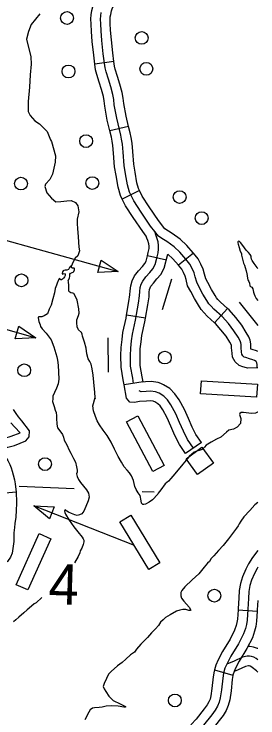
# Model space of a CAD drawing. Extents: x 653372 to 905732, y 627442 to 787275.
# Drawn here: x 726770 to 728673, y 744286 to 749788 of the extents above; entities that cross this region are included whole.
import ezdxf

# ---------------------------------------------------------------- set-up
doc = ezdxf.new("R2010")
doc.units = 0
for name, color, linetype in [('32', 7, 'Continuous'), ('35', 7, 'Continuous'), ('45', 7, 'Continuous'), ('5', 7, 'Continuous'), ('56', 7, 'Continuous'), ('57', 7, 'Continuous'), ('9', 7, 'Continuous')]:
    doc.layers.add(name, color=color, linetype=linetype)

msp = doc.modelspace()

# ---------------------------------------------------------------- linework, layer by layer
at = {"layer": '32'}
for p, q in [((727549, 749417.2), (727400.3, 749397.6)), ((727662.8, 748910.5), (727516.8, 748876.1)), ((727748.1, 748408.3), (727613.4, 748342.4)), ((727958.1, 747865.3), (727811.6, 747897.1)), ((728170.2, 747919.1), (728052.5, 747826.1)), ((727795.8, 747409.9), (727648, 747435.3)), ((728435.5, 747486.9), (728335.1, 747375.5)), ((728672.8, 747022.8), (728590.8, 747020.6)), ((727776.6, 746912), (727628.4, 746889)), ((728517.5, 745130.9), (728667.2, 745121.7)), ((728334.1, 744661), (728478.3, 744619.7))]:
    msp.add_line(p, q, dxfattribs=at)
for points in [[(727400.3, 749397.6), (727391, 749467.9), (727380, 749573.8), (727373.7, 749651.4), (727370.6, 749709.6), (727369.8, 749750), (727370.7, 749781.4), (727376.6, 749815.2), (727386.4, 749854.6), (727399, 749893.2), (727420.4, 749938.1), (727430.9, 749958.4)], [(727549, 749417.2), (727540, 749485.5), (727529.3, 749587.7), (727523.4, 749661.4), (727520.5, 749715.1), (727519.8, 749749.2), (727520.4, 749766.2), (727523.5, 749784.3), (727530.7, 749813.2), (727538.5, 749837.3), (727554.9, 749871.5), (727564.3, 749889.9)], [(727444.8, 749749.6), (727445.5, 749773.8), (727450.1, 749799.7)], [(727702.5, 746900.5), (727696.3, 746940.7), (727679.5, 747034.5), (727678.4, 747119.3), (727680.1, 747176.1), (727687.4, 747234.5), (727692.8, 747286.9), (727717.4, 747396.6), (727740, 747528.1), (727749.2, 747585.9), (727750.2, 747619.4), (727753.9, 747650), (727761.2, 747675.9), (727774.1, 747701.5), (727799.2, 747733.4), (727828.2, 747767), (727853.2, 747796), (727871, 747829.9), (727884.6, 747880.7), (727893.3, 747920.5), (727897.9, 747950.2), (727897.8, 747978.1), (727894, 748007.1), (727884.8, 748040), (727877, 748061.6), (727867.6, 748088), (727834.4, 748131.3), (727762.3, 748240.5), (727704.4, 748327), (727670.2, 748397), (727654.2, 748452.4), (727640.3, 748539), (727629.2, 748604.5), (727621.2, 748708.1), (727615.6, 748770.6), (727609.3, 748809.9), (727601.9, 748841.8), (727570.5, 748975), (727551.3, 749079.2), (727547, 749120.4), (727540.7, 749159.7), (727523.9, 749219.8), (727506.1, 749279), (727487.3, 749336.3), (727479.9, 749367.3), (727465.5, 749476.7), (727454.6, 749580.8), (727448.5, 749656.4), (727445.6, 749712.3), (727444.8, 749749.6)], [(727662.8, 748910.5), (727643.9, 748990.4), (727625.6, 749090), (727621.3, 749130.2), (727614.1, 749175.7), (727595.9, 749240.6), (727577.7, 749301.4), (727559.6, 749356.8), (727553.7, 749381), (727549, 749417.2)], [(727516.8, 748876.1), (727497.1, 748959.6), (727477, 749068.5), (727472.6, 749110.5), (727467.3, 749143.6), (727451.8, 749198.9), (727434.5, 749256.5), (727415.1, 749315.9), (727406, 749353.6), (727400.3, 749397.6)], [(727613.4, 748342.4), (727599.9, 748369.9), (727580.8, 748436), (727566.3, 748526.8), (727554.7, 748595.3), (727546.4, 748701.9), (727541.1, 748761.4), (727535.7, 748795.5), (727528.9, 748824.7), (727516.8, 748876.1)], [(727748.1, 748408.3), (727740.4, 748424.1), (727727.5, 748468.8), (727714.3, 748551.1), (727703.7, 748613.6), (727695.9, 748714.3), (727690.1, 748779.9), (727683, 748824.4), (727674.9, 748858.9), (727662.8, 748910.5)], [(727946.6, 748108.2), (727895.6, 748174.8), (727824.8, 748282.1), (727769.5, 748364.5), (727748.1, 748408.3)], [(727817.4, 747924.3), (727819.5, 747934.3), (727822.9, 747955.9), (727822.8, 747973.1), (727820.3, 747992), (727813.3, 748017.2), (727806.4, 748036.4), (727800.9, 748051.7), (727773.3, 748087.8), (727699.9, 748199), (727639.2, 748289.5), (727613.4, 748342.4)], [(728170.2, 747919.1), (728168.4, 747921.3), (728118.3, 747978.9), (728066.9, 748027.5), (728004.4, 748073.2), (727946.6, 748108.2)], [(728666.4, 747029), (728667.5, 747048.6), (728664.5, 747061), (728658.7, 747071.3), (728646.6, 747079.5), (728633.9, 747086.1), (728606.1, 747094.2), (728579.4, 747102.3), (728565, 747107.2), (728554.1, 747116.5), (728547.7, 747128.5), (728545.4, 747145.4), (728541.5, 747182.5), (728542.1, 747205.3), (728540.3, 747217.2), (728533.4, 747233.1), (728517.5, 747261.6), (728485.9, 747313), (728442.2, 747368.2), (728394.5, 747422.9), (728329.2, 747481.8), (728307.4, 747504.3), (728288.9, 747523.4), (728273.4, 747549.7), (728244.2, 747599.8), (728215.6, 747654.5), (728194.8, 747692.1), (728184.3, 747734.5), (728174.2, 747766.6), (728159.5, 747799.5), (728142, 747833.7), (728110.7, 747873.4), (728064.1, 747926.9), (728018.8, 747969.8), (727962.8, 748010.8), (727923.7, 748034.4), (727896.3, 748053.1), (727867.6, 748088)], [(727648, 747435.3), (727666, 747540.4), (727674.3, 747592.9), (727675.3, 747625), (727680.1, 747664.8), (727690.9, 747703.1), (727710.4, 747742), (727741.4, 747781.1), (727771.4, 747816), (727790.8, 747838.5), (727800.7, 747857.4), (727811.7, 747898.4), (727817.4, 747924.4)], [(727795.8, 747409.9), (727814, 747515.9), (727824, 747578.8), (727825, 747613.7), (727827.6, 747635.2), (727831.4, 747648.6), (727837.7, 747661.1), (727857.1, 747685.6), (727884.9, 747718), (727915.6, 747753.5), (727941.3, 747802.5), (727970.7, 747912.1)], [(728052.9, 747825.5), (728009.9, 747875), (727970.7, 747912.1)], [(728435.5, 747486.9), (728381.3, 747535.8), (728361.3, 747556.5), (728349, 747569.2), (728338.2, 747587.6), (728309.9, 747636.1), (728281.7, 747690), (728265.3, 747719.7), (728256.6, 747754.9), (728244.4, 747793.2), (728227.2, 747831.9), (728205.4, 747874.4), (728170.2, 747919.1)], [(728335.1, 747375.5), (728277, 747427.8), (728253.5, 747452.2), (728228.8, 747477.6), (728208.7, 747511.7), (728178.6, 747563.5), (728149.5, 747619), (728124.4, 747664.6), (728112.1, 747714.2), (728104, 747739.9), (728091.8, 747767.2), (728078.6, 747793), (728052.5, 747826.1)], [(727628.4, 746889), (727622.3, 746928.4), (727604.6, 747027.4), (727603.4, 747119.9), (727605.2, 747181.9), (727612.9, 747243), (727618.6, 747299), (727643.8, 747411.1), (727648, 747435.3)], [(728672.8, 747150.4), (728661.9, 747156), (728627.5, 747166.1), (728618.3, 747168.9), (728616.6, 747185.4), (728617.3, 747210.1), (728612.9, 747238.1), (728600.8, 747266.2), (728582.2, 747299.5), (728547.5, 747356.1), (728499.8, 747416.2), (728448, 747475.6), (728435.5, 747486.9)], [(727776.6, 746912), (727770.3, 746953), (727754.5, 747041.7), (727753.4, 747118.7), (727754.9, 747170.2), (727761.9, 747226), (727767, 747274.8), (727791, 747382), (727795.8, 747409.9)], [(728590.8, 747020.6), (728584.7, 747022.3), (728556.4, 747030.9), (728527.3, 747040.8), (728494.6, 747068.7), (728475.2, 747105.1), (728470.9, 747136.4), (728466.3, 747179.7), (728466.9, 747198), (728466.1, 747199.9), (728452.8, 747223.7), (728424.4, 747270), (728384.5, 747320.2), (728340.9, 747370.2), (728335.1, 747375.5)], [(728672.8, 745594.8), (728629.7, 745539.9), (728600.4, 745489.7), (728577.9, 745448), (728551.7, 745389), (728537.3, 745337.8), (728527.1, 745281.9), (728523.8, 745223.1), (728518, 745140.1), (728517.5, 745130.9)], [(728672.8, 745465), (728665.8, 745453), (728645.3, 745414.9), (728622.4, 745363.5), (728610.5, 745320.9), (728601.7, 745273.1), (728598.7, 745218.4), (728592.9, 745135.1), (728587.7, 745050.5), (728583.3, 745015.9), (728574.7, 744985.6), (728560.6, 744942.3), (728520.9, 744865.4), (728462.6, 744767.7), (728429.6, 744706.6), (728415.7, 744673.6), (728404.5, 744634.6), (728398, 744596.7), (728388.7, 744506.7), (728379.4, 744442.8), (728370.4, 744408.4), (728357.5, 744378.7), (728339.1, 744346.6), (728312, 744311.3), (728247.5, 744229.2)], [(728672.8, 745202.8), (728667.7, 745130.2), (728667.2, 745121.7)], [(728517.5, 745130.9), (728512.9, 745057.5), (728509.6, 745031), (728502.9, 745007.5), (728491.1, 744971.3), (728455.3, 744901.8), (728397.3, 744804.7), (728361.8, 744739.1), (728344.8, 744698.5), (728334.1, 744661)], [(728667.2, 745121.7), (728662.4, 745043.5), (728657, 745000.9), (728646.4, 744963.8), (728630, 744913.3), (728586.5, 744828.9), (728527.8, 744730.6), (728497.3, 744674.2), (728486.6, 744648.7), (728478.3, 744619.7)], [(728334.1, 744661), (728331.3, 744651.2), (728323.7, 744606.9), (728314.2, 744515.9), (728305.8, 744457.8), (728299.3, 744433), (728290.3, 744412.4), (728276.5, 744388.2), (728252.8, 744357.4), (728189.8, 744277.1), (728151.6, 744233.6), (728148.1, 744230.5)], [(728478.3, 744619.7), (728477.7, 744617.9), (728472.4, 744586.5), (728463.1, 744497.4), (728453, 744427.9), (728441.4, 744383.8), (728424.6, 744345.1), (728401.7, 744305), (728371.3, 744265.3), (728288.8, 744160.3)]]:
    msp.add_lwpolyline(points, dxfattribs=at)
at = {"layer": '35'}
for points in [[(726969.3, 749788.9), (726903.8, 749707.1), (726880.8, 749652.7), (726867.7, 749592.6), (726899.9, 749453.2), (726903.8, 749396.6), (726895.3, 749313.6), (726889.3, 749217.5), (726880.3, 749104.6), (726878.8, 749027.5)], [(726878.8, 749027.5), (726896.1, 748995.2), (726932.3, 748953), (726967.7, 748929), (727027.8, 748870.3), (727053.7, 748804.1), (727062.4, 748792.8), (727092.2, 748679.5), (727090.2, 748629.6), (727068.7, 748537.8)], [(727068.7, 748537.8), (727049.9, 748495.5), (727013.8, 748459.8), (727009.8, 748439.9), (727025.1, 748390.9), (727062.2, 748348), (727096.5, 748320.3), (727133.3, 748322.2), (727182, 748329.4), (727215.4, 748329.7), (727250.1, 748315.6), (727266, 748288.4), (727274.7, 748243), (727262.9, 748184.9), (727261.8, 748148.1), (727265.8, 748112.9), (727268.8, 748045.9), (727274.7, 747967.2), (727278.9, 747936.9), (727267.6, 747897.2), (727245.4, 747879.4), (727229.5, 747851.5), (727214.5, 747815.8)]]:
    msp.add_lwpolyline(points, dxfattribs=at)
at = {"layer": '45'}
for p, q in [((728232.3, 746438.1), (728108.7, 746353.2)), ((726635.6, 746041.2), (726785.1, 746053.6))]:
    msp.add_line(p, q, dxfattribs=at)
for points in [[(727860.1, 746759.8), (727855.7, 746761.6), (727832.7, 746764.4), (727803.7, 746763.1), (727749.3, 746759.3), (727710.7, 746751.8), (727671.9, 746755), (727646.3, 746786.4), (727628.4, 746889)], [(727916, 746899), (727893.6, 746908), (727838.6, 746914.9), (727795, 746912.8), (727774.7, 746911.4), (727774.7, 746911.4)], [(728232.3, 746438.1), (728188.7, 746501.7), (728159.3, 746558.9), (728129.8, 746625.4), (728099, 746697.2), (728057.5, 746772.8), (728025, 746820.1), (727986.1, 746860.2), (727936.1, 746890.9), (727916, 746899)], [(728170.5, 746395.6), (728124.1, 746463.1), (728091.6, 746526.5), (728061.1, 746595.4), (728031.5, 746664.3), (727993.5, 746733.4), (727966.8, 746772.4), (727938.8, 746801.2), (727902.2, 746823.7), (727874.6, 746834.8), (727835.7, 746839.7), (727799.3, 746838), (727762, 746835.4), (727745.5, 746842.4)], [(728108.7, 746353.2), (728059.6, 746424.6), (728023.9, 746494.2), (727992.3, 746565.4), (727964, 746631.4), (727929.6, 746694), (727908.6, 746724.7), (727891.5, 746742.2), (727868.4, 746756.5), (727860.1, 746759.8)], [(726662.7, 746381.1), (726721.4, 746401.8), (726771.9, 746416.5), (726861.1, 746452.8), (726887.5, 746483), (726888.9, 746529.4), (726829.8, 746608.6), (726803.2, 746640.5), (726785.1, 746664.5), (726766.2, 746697.9), (726766.3, 746697.8)], [(726817.9, 746514.3), (726774.3, 746558), (726744.4, 746593.9)], [(726492.6, 746424.2), (726516.8, 746426.9), (726554.4, 746435.3), (726613.9, 746447.9), (726662.1, 746460.4), (726698.4, 746473.3), (726748, 746487.7), (726817.9, 746514.3)], [(726662.7, 746381.1), (726697.1, 746335.8), (726720.2, 746298.2), (726736.9, 746266.9), (726746.8, 746240.2), (726753.7, 746214.3), (726761.8, 746187.2), (726772.4, 746147.6), (726777.8, 746115.2), (726783.5, 746072.1), (726785.1, 746053.6)], [(726785.1, 746053.6), (726787.1, 746028.6), (726788.2, 745992.4), (726788.9, 745960.9), (726786.8, 745909.5), (726784.1, 745855), (726776.2, 745805.8), (726771.6, 745774.5), (726768, 745731.9), (726766.5, 745664.5), (726761, 745610.1), (726755, 745573.6), (726742.4, 745542.9), (726718.8, 745507.9), (726673.6, 745490.1), (726643, 745492.9), (726617.2, 745498.4), (726584.9, 745515.8), (726574.8, 745526.1)], [(728672.8, 744828.5), (728670.2, 744829.9), (728639.5, 744840.2), (728611.1, 744844.5), (728594.3, 744844)], [(728672.8, 744740.6), (728658.2, 744751.5), (728640.7, 744760.7), (728621.9, 744767), (728606.5, 744769.3), (728588.7, 744768.8), (728551.9, 744760.3), (728487.9, 744730.4), (728429.6, 744706.6)], [(728614.4, 744689.8), (728611.2, 744691.5), (728604.2, 744693.8), (728601.9, 744694.2), (728598.3, 744694.1), (728576.5, 744689), (728517.9, 744661.7), (728486.7, 744648.9)], [(728672.8, 744644.1), (728661.7, 744653.8), (728627.4, 744680.9), (728618.1, 744687.8), (728614.4, 744689.8)]]:
    msp.add_lwpolyline(points, dxfattribs=at)
at = {"layer": '5'}
for points in [[(727239.8, 746076.1), (726808.9, 746094.2)], [(727863.2, 746049.8), (727769.9, 746053.7)]]:
    msp.add_lwpolyline(points, dxfattribs=at)
at = {"layer": '56'}
for p, q in [((727422.1, 747767.2), (727449.5, 747865.4)), ((727449.5, 747865.4), (727583.2, 747775.2)), ((727583.2, 747775.2), (727422.1, 747767.2)), ((726778.2, 747249.5), (726806.3, 747347.5)), ((726806.3, 747347.5), (726939.3, 747256.2)), ((726939.3, 747256.2), (726778.2, 747249.5)), ((727046, 745841.3), (726922.6, 745945.1)), ((726922.6, 745945.1), (727083.6, 745936.1)), ((727083.6, 745936.1), (727046, 745841.3))]:
    msp.add_line(p, q, dxfattribs=at)
for points in [[(726156.2, 748637.7), (726026.1, 748209.4), (727583.2, 747775.2)], [(727999.3, 747716.2), (727926.7, 747477)], [(728526.4, 747536.1), (728672.8, 747352.4)], [(726373.8, 747418.8), (726939.3, 747256.2)], [(727502.6, 747257.9), (727502.7, 746987.9)], [(727708.4, 745633.1), (726922.6, 745945.1)]]:
    msp.add_lwpolyline(points, dxfattribs=at)
for points in [[(728226, 746820), (728231.9, 746919.8), (728668.6, 746894.1), (728662.7, 746794.3)], [(727646.7, 746599.7), (727735, 746646.5), (727939.8, 746259.9), (727851.4, 746213.1)], [(727594.6, 745819.9), (727680, 745872), (727907.7, 745498.4), (727822.3, 745446.4)], [(726964.5, 745726.5), (727055.8, 745685.6), (726877.2, 745286.3), (726785.9, 745327.1)]]:
    msp.add_lwpolyline(points, close=True, dxfattribs=at)
for centre in [(727182.8, 749757.4), (727765.5, 749602), (727194.1, 749339.4), (727801.7, 749360.1), (727331.9, 748795), (726823, 748463), (727380.1, 748467.1), (728061.8, 748357.7), (728234, 748193), (726827.2, 747706.5), (727946.2, 747102.7), (726848.7, 747004), (727010.6, 746270.1), (728333.1, 745241.2), (728024.7, 744422.3)]:
    msp.add_circle(centre, 50, dxfattribs=at)
at = {"layer": '57'}
msp.add_lwpolyline([(728202, 746187.8), (728111.7, 746311.3), (728235.2, 746401.6), (728325.5, 746278.1)], close=True, dxfattribs=at)
at = {"layer": '9'}
for points in [[(728672.8, 747797.6), (728667, 747805.9), (728644.4, 747838.5), (728627.8, 747863.1), (728622.5, 747873.4), (728619.5, 747886.4), (728619.8, 747895.9), (728611.2, 747907.9), (728599.3, 747923.4), (728581.4, 747943.6), (728555.5, 747978.6), (728536.1, 748002.8), (728529, 748010.8), (728520.7, 748012.1), (728514.9, 748007.9), (728516.4, 747999.4), (728520, 747988.7), (728527.6, 747963.2), (728534, 747934.9), (728544.7, 747915.6), (728546, 747903.2), (728548.7, 747882.9), (728559.3, 747842.2), (728568.3, 747825.7), (728573.4, 747806.4), (728581.6, 747780.9), (728587.1, 747758.3), (728589.4, 747743.7), (728591.5, 747720.1), (728595.2, 747710.4), (728601, 747698.5), (728606.7, 747683.7), (728610, 747663.4), (728615.5, 747658.8), (728625.4, 747652.3), (728632.3, 747640.9), (728635.9, 747628.4), (728639.3, 747613.2), (728642.8, 747599), (728649.1, 747584.8), (728659.8, 747565.4), (728672.8, 747548.4)], [(727240.9, 747800.1), (727239.5, 747802.8), (727229.1, 747802.2), (727226.3, 747802.4), (727223.5, 747803.5), (727214.5, 747815.8), (727210.1, 747818.1), (727201.8, 747806.9), (727194, 747792.6), (727180.4, 747786.3), (727167.5, 747785.5), (727157.9, 747784.1), (727151.6, 747780.4), (727146.9, 747773.2), (727144.3, 747760.4), (727144.2, 747757.1), (727150.3, 747754.1), (727152, 747756.3), (727160.5, 747759.9), (727167.7, 747756.9), (727168.2, 747752.4), (727167.9, 747744.6), (727162.4, 747733), (727157.3, 747726.4), (727154.7, 747720.1), (727148.5, 747715), (727140.5, 747710.6), (727133.2, 747710.3), (727130.5, 747713.2), (727128.4, 747718.3), (727124.6, 747721.2), (727122.9, 747720.1), (727119.4, 747715.7), (727106.1, 747683.6), (727101.7, 747669.7), (727089.7, 747643.1), (727084.3, 747609.2)], [(727301.8, 747284.7), (727294.7, 747298.6), (727273.4, 747320.2), (727261.3, 747344), (727260, 747374.3), (727258.5, 747397.9), (727271.4, 747432.1), (727277.5, 747449.8), (727275.6, 747484.9), (727260.8, 747551.6), (727246.1, 747585.7), (727236.6, 747603.9), (727227.7, 747607), (727213.2, 747608.6), (727204.4, 747613.3), (727197.9, 747621.4), (727197.1, 747632), (727197, 747667.4), (727193.3, 747694.4), (727192.6, 747705.7), (727201, 747724.5), (727204.8, 747740.1), (727205.5, 747754.1), (727208.7, 747761.9), (727211.8, 747764), (727223.6, 747767.6), (727231.4, 747770.5), (727236.6, 747776.4), (727239.9, 747788.4), (727240.9, 747800.1)], [(727084.3, 747609.2), (727073, 747562.7), (727058.6, 747513.7), (727042.8, 747480.2), (727029.4, 747446), (727018, 747436.5), (727004.2, 747429.5), (726986.1, 747422.6), (726962.6, 747420.9), (726958.3, 747419.2), (726958.1, 747413), (726962.1, 747383.9), (726973.7, 747358.2), (726974.5, 747344.6), (726988.2, 747328.1), (727019.9, 747292.6), (727043.1, 747262.9), (727058.5, 747241.7), (727080.3, 747186.7), (727103.3, 747109.4), (727108.6, 747082.1), (727114.2, 747043), (727116.3, 746989.7), (727117.7, 746934.1), (727112.9, 746896.6), (727101.5, 746864.8), (727085, 746829.5), (727072.4, 746802.1), (727073, 746781.1), (727069.9, 746759.5), (727073.8, 746744), (727081.7, 746720.3), (727091.3, 746691), (727098.2, 746672.3), (727101.2, 746648.7), (727101.8, 746629), (727102.2, 746582.1), (727108.2, 746552.9), (727126, 746531.4), (727148.6, 746500.8), (727154.1, 746480.3), (727160.8, 746457.3), (727180.7, 746420.2), (727199.2, 746379.5), (727211.5, 746356.3), (727234.3, 746314.3), (727249.5, 746285.4), (727257.1, 746249.4), (727262.4, 746222.1), (727260.7, 746207.3), (727256.4, 746193), (727260.7, 746173.1), (727271.7, 746148.7), (727287.7, 746125.3), (727334.2, 746068.4)], [(727404.7, 746780.9), (727402.8, 746789.7), (727399.5, 746830.2), (727391.9, 746910.4), (727387.9, 746966.6), (727378.1, 747014), (727371.4, 747050.1), (727359.7, 747072.9), (727346.9, 747093.5), (727336.8, 747131.9), (727331.4, 747177), (727319.4, 747224.5), (727304, 747270.9), (727301.8, 747284.7)], [(727890.4, 746034.5), (727849.2, 745989.6), (727824, 745971.3), (727794.4, 745957.6), (727783.1, 745953.4), (727775.3, 745953.7), (727764.4, 745965.2), (727762.7, 745983.2), (727752.7, 746023.9), (727737.7, 746046.8), (727721.6, 746071.9), (727711.1, 746095.8), (727701.3, 746143.2), (727685.6, 746178.5), (727670.5, 746201.4), (727653.2, 746222.1), (727629.4, 746249.7), (727608, 746286.3), (727581.3, 746329.7), (727553.9, 746387.7), (727526.3, 746441.3), (727496.5, 746494.9), (727465.2, 746535.1), (727437.3, 746577.5), (727417, 746608.4), (727404.5, 746641.3), (727389, 746685.5), (727383.5, 746724.9), (727402.8, 746789.7)], [(728672.8, 746677.3), (728668.9, 746675.3), (728653, 746667.9), (728623.8, 746666.6), (728560.1, 746674.1), (728543.3, 746674.6), (728533, 746667), (728528.2, 746657.1), (728540.8, 746627.5), (728537.3, 746587.3), (728511.8, 746560), (728482.2, 746544), (728447.1, 746535), (728426.5, 746519.9), (728382.7, 746482), (728349.7, 746465), (728307.5, 746442.7), (728268.6, 746417), (728257, 746403.8), (728237.3, 746383.1), (728214.7, 746377.1), (728195.5, 746372), (728175.1, 746363.7), (728156.7, 746348.5), (728135.9, 746330.1), (728113.7, 746300.4), (728087, 746269.9), (728025.3, 746193.2), (727993.9, 746157.1), (727975.4, 746136.4), (727947.9, 746117), (727915, 746068.6), (727894, 746042.3), (727890.4, 746034.5)], [(727334.2, 746068.4), (727351.2, 746043.8), (727354.6, 746011), (727348.2, 745983.4), (727330.2, 745938.9), (727313, 745902.3), (727299.4, 745881.1), (727280.6, 745872.4), (727260.8, 745869.3), (727244.3, 745874.8), (727217.4, 745883.6), (727193.7, 745894.8), (727180.3, 745903.2), (727172.6, 745910.9), (727168.3, 745912.2), (727163.1, 745905), (727165.8, 745891.9), (727172.2, 745879.4), (727200.4, 745832.1), (727237.1, 745779.7), (727267.5, 745741.7), (727300.1, 745698.2), (727308.4, 745686.2), (727313, 745674.3), (727313.8, 745661.9), (727309.5, 745642.3), (727297.5, 745611.8), (727285.8, 745592.4), (727281.6, 745576.5), (727269.2, 745547.7), (727240.7, 745499.2)], [(728672.8, 745970.2), (728649.8, 745951.3), (728608.6, 745907.8), (728563.1, 745857), (728538.6, 745824.4), (728526.6, 745804.4), (728517.9, 745788.4), (728506.8, 745770), (728443.3, 745687.2), (728401, 745634.8), (728364.9, 745596), (728328.6, 745553.1), (728308.5, 745533.3), (728294.7, 745507.7), (728279.6, 745495.1), (728254.3, 745465), (728212.9, 745413.3), (728160.2, 745366), (728102.4, 745310), (728079.6, 745282.2), (728071.7, 745265.3), (728071.8, 745240.9), (728075.3, 745222), (728094.1, 745198.7), (728135, 745151.3), (728147.6, 745134.6), (728148.2, 745128.1), (728144.9, 745126.6), (728134.3, 745126.9), (728110.1, 745132.5), (728088.1, 745133.2), (728062.7, 745127.4), (728037.2, 745119.2), (727986.8, 745093.1), (727951.2, 745071.3), (727932.7, 745054), (727913.4, 745033.4), (727897.2, 745008.7), (727872.8, 744983.3), (727842.6, 744950.9), (727811.4, 744914.4), (727758.5, 744862.2), (727725.6, 744823.3), (727708.7, 744801), (727679.5, 744778.3), (727641.9, 744744.4), (727613.4, 744718.4), (727576.9, 744694.3)], [(726986.1, 745228.3), (726941.1, 745185.3), (726926.6, 745176.5), (726905.7, 745159.9)], [(726905.7, 745159.9), (726871.2, 745130.9), (726845.2, 745107.6), (726806.6, 745074.2), (726783.1, 745053.9), (726764.1, 745037.8)], [(727576.9, 744694.3), (727528.3, 744648.5), (727507.3, 744627.2), (727490.9, 744594.3), (727471.8, 744554.2), (727464.6, 744532.4), (727472.2, 744513.4), (727484.6, 744492.7), (727509.5, 744456.1), (727542.7, 744422.6), (727597.3, 744397.3), (727634.9, 744378.3), (727641.3, 744372.4), (727636.3, 744370.9), (727627.4, 744370.4), (727582.8, 744376.6), (727528.4, 744379.9), (727488.4, 744377), (727457.3, 744370.6), (727434.4, 744368), (727398.5, 744365), (727381.3, 744361.5), (727363.8, 744348.2), (727352.8, 744332.2), (727322.4, 744270.5)]]:
    msp.add_lwpolyline(points, dxfattribs=at)

# ---------------------------------------------------------------- texts
at = {"layer": '56'}
msp.add_text('4', height=316.8, rotation=358.28, dxfattribs=at).set_placement((727035.6, 745175.6))

doc.saveas('drawing.dxf')
